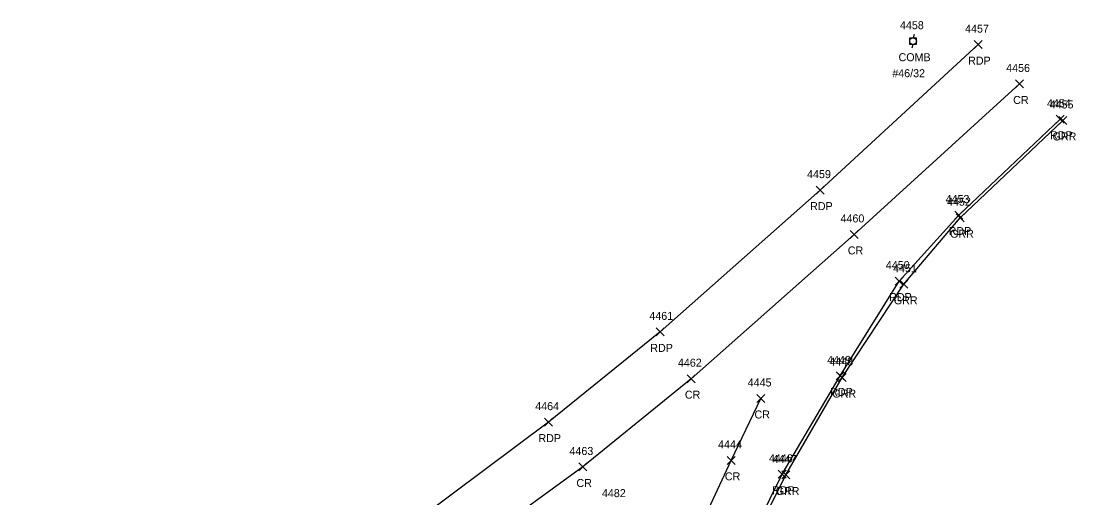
# Model space of a CAD drawing. Extents: x 1690689 to 1696275, y 438760 to 444007.
# Drawn here: x 1696011 to 1696274.6, y 443678 to 443797.2 of the extents above; entities that cross this region are included whole.
import ezdxf

# ---------------------------------------------------------------- set-up
doc = ezdxf.new("R2010")
doc.units = 0
for name, color, linetype in [('P_A', 7, 'Continuous'), ('P_I', 7, 'Continuous'), ('P_TIC', 7, 'Continuous'), ('PET', 7, 'Continuous'), ('PRC', 7, 'Continuous'), ('R_A', 7, 'Continuous'), ('R_I', 7, 'Continuous'), ('R_TIC', 7, 'Continuous'), ('RGR', 7, 'Continuous'), ('U_A', 7, 'Continuous'), ('U_C', 7, 'Continuous'), ('U_I', 7, 'Continuous'), ('UP', 7, 'Continuous')]:
    doc.layers.add(name, color=color, linetype=linetype)

msp = doc.modelspace()

# ---------------------------------------------------------------- linework, layer by layer
at = {"layer": 'P_TIC'}
for points in [[(1696249.19, 443790.3), (1696251.19, 443792.3)], [(1696251.19, 443790.3), (1696249.19, 443792.3)], [(1696259.51, 443780.47), (1696261.51, 443782.47)], [(1696261.51, 443780.47), (1696259.51, 443782.47)], [(1696269.65, 443771.67), (1696271.65, 443773.67)], [(1696271.65, 443771.67), (1696269.65, 443773.67)], [(1696209.71, 443753.93), (1696211.71, 443755.93)], [(1696211.71, 443753.93), (1696209.71, 443755.93)], [(1696244.32, 443747.71), (1696246.32, 443749.71)], [(1696246.32, 443747.71), (1696244.32, 443749.71)], [(1696218.19, 443742.86), (1696220.19, 443744.86)], [(1696220.19, 443742.86), (1696218.19, 443744.86)], [(1696229.46, 443731.21), (1696231.46, 443733.21)], [(1696231.46, 443731.21), (1696229.46, 443733.21)], [(1696169.77, 443718.49), (1696171.77, 443720.49)], [(1696171.77, 443718.49), (1696169.77, 443720.49)], [(1696177.48, 443706.8), (1696179.48, 443708.8)], [(1696179.48, 443706.8), (1696177.48, 443708.8)], [(1696214.73, 443707.5), (1696216.73, 443709.5)], [(1696216.73, 443707.5), (1696214.73, 443709.5)], [(1696194.87, 443701.85), (1696196.87, 443703.85)], [(1696196.87, 443701.85), (1696194.87, 443703.85)], [(1696141.82, 443695.93), (1696143.82, 443697.93)], [(1696143.82, 443695.93), (1696141.82, 443697.93)], [(1696187.46, 443686.38), (1696189.46, 443688.38)], [(1696189.46, 443686.38), (1696187.46, 443688.38)], [(1696150.38, 443684.72), (1696152.38, 443686.72)], [(1696152.38, 443684.72), (1696150.38, 443686.72)], [(1696200.23, 443682.9), (1696202.23, 443684.9)], [(1696202.23, 443682.9), (1696200.23, 443684.9)]]:
    msp.add_lwpolyline(points, dxfattribs=at)
at = {"layer": 'PET'}
for points in [[(1696250.19, 443791.3), (1696210.71, 443754.93), (1696170.77, 443719.49), (1696142.82, 443696.93), (1696110.55, 443672.79), (1696083.77, 443655.61), (1696046.88, 443637.17), (1696007.3, 443622.08), (1695975.79, 443612.67), (1695948.64, 443606.07)], [(1696105.95, 443484.07), (1696183.09, 443647.09), (1696201.23, 443683.9), (1696215.73, 443708.5), (1696230.46, 443732.21), (1696245.32, 443748.71), (1696270.65, 443772.67)]]:
    msp.add_lwpolyline(points, dxfattribs=at)
at = {"layer": 'PRC'}
for points in [[(1696260.51, 443781.47), (1696219.19, 443743.86), (1696178.48, 443707.8), (1696151.38, 443685.72), (1696117.73, 443661.29), (1696090.79, 443644.23), (1696052.24, 443624.84), (1696014.43, 443610.17)], [(1696096.07, 443488.52), (1696171.55, 443651.03), (1696188.46, 443687.38), (1696195.87, 443702.85)]]:
    msp.add_lwpolyline(points, dxfattribs=at)
at = {"layer": 'R_TIC'}
for points in [[(1696270.31, 443771.35), (1696272.31, 443773.35)], [(1696272.31, 443771.35), (1696270.31, 443773.35)], [(1696244.68, 443747.04), (1696246.68, 443749.04)], [(1696246.68, 443747.04), (1696244.68, 443749.04)], [(1696230.62, 443730.39), (1696232.62, 443732.39)], [(1696232.62, 443730.39), (1696230.62, 443732.39)], [(1696215.25, 443707.09), (1696217.25, 443709.09)], [(1696217.25, 443707.09), (1696215.25, 443709.09)], [(1696201.1, 443682.72), (1696203.1, 443684.72)], [(1696203.1, 443682.72), (1696201.1, 443684.72)]]:
    msp.add_lwpolyline(points, dxfattribs=at)
at = {"layer": 'RGR'}
msp.add_lwpolyline([(1696106.25, 443483.86), (1696183.75, 443646.63), (1696202.1, 443683.72), (1696216.25, 443708.09), (1696231.62, 443731.39), (1696245.68, 443748.04), (1696271.31, 443772.35)], dxfattribs=at)
at = {"layer": 'UP'}
for p, q in [((1696233.08, 443791.33), (1696233.08, 443792.99)), ((1696233.08, 443792.99), (1696234.74, 443792.99)), ((1696234.16, 443793.83), (1696233.91, 443792.99)), ((1696234.74, 443792.99), (1696234.74, 443791.33)), ((1696234.74, 443791.33), (1696233.08, 443791.33)), ((1696233.66, 443790.49), (1696233.91, 443791.33)), ((1696233.91, 443792.16), (1696233.91, 443792.16))]:
    msp.add_line(p, q, dxfattribs=at)
msp.add_circle((1696233.91, 443792.16), 0.833, dxfattribs=at)

# ---------------------------------------------------------------- texts
at = {"layer": 'P_A'}
for s, p in [('RDP', (1696247.68, 443786.3)), ('CR', (1696258.94, 443776.47)), ('RDP', (1696268.14, 443767.67)), ('RDP', (1696208.2, 443749.93)), ('RDP', (1696242.81, 443743.71)), ('CR', (1696217.62, 443738.86)), ('RDP', (1696227.95, 443727.21)), ('RDP', (1696168.26, 443714.49)), ('RDP', (1696213.22, 443703.5)), ('CR', (1696176.91, 443702.8)), ('CR', (1696194.3, 443697.85)), ('RDP', (1696140.31, 443691.93)), ('CR', (1696186.9, 443682.38)), ('CR', (1696149.81, 443680.72)), ('RDP', (1696198.71, 443678.9))]:
    msp.add_text(s, height=2, dxfattribs=at).set_placement(p)
at = {"layer": 'P_I'}
for s, p in [('4457', (1696246.93, 443794.3)), ('4456', (1696257.19, 443784.47)), ('4454', (1696267.39, 443775.67)), ('4459', (1696207.44, 443757.93)), ('4453', (1696242.06, 443751.71)), ('4460', (1696215.8, 443746.86)), ('4450', (1696227.12, 443735.21)), ('4461', (1696168.03, 443722.49)), ('4449', (1696212.47, 443711.5)), ('4462', (1696175.17, 443710.8)), ('4445', (1696192.61, 443705.85)), ('4464', (1696139.52, 443699.93)), ('4444', (1696185.2, 443690.38)), ('4463', (1696148.07, 443688.72)), ('4446', (1696197.91, 443686.9)), ('4482', (1696156.18, 443678.19))]:
    msp.add_text(s, height=2, dxfattribs=at).set_placement(p)
at = {"layer": 'R_A'}
for p in [(1696268.79, 443767.35), (1696243.16, 443743.04), (1696229.11, 443726.39), (1696213.74, 443703.09), (1696199.59, 443678.72)]:
    msp.add_text('GRR', height=2, dxfattribs=at).set_placement(p)
at = {"layer": 'R_I'}
for s, p in [('4455', (1696268.05, 443775.35)), ('4452', (1696242.42, 443751.04)), ('4451', (1696228.93, 443734.39)), ('4448', (1696212.99, 443711.09)), ('4447', (1696198.84, 443686.72))]:
    msp.add_text(s, height=2, dxfattribs=at).set_placement(p)
at = {"layer": 'U_A'}
msp.add_text('COMB', height=2, dxfattribs=at).set_placement((1696230.3, 443787.16))
at = {"layer": 'U_C'}
msp.add_text('#46/32', height=2, dxfattribs=at).set_placement((1696228.73, 443783.16))
at = {"layer": 'U_I'}
msp.add_text('4458', height=2, dxfattribs=at).set_placement((1696230.65, 443795.16))

doc.saveas('drawing.dxf')
